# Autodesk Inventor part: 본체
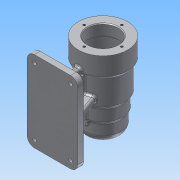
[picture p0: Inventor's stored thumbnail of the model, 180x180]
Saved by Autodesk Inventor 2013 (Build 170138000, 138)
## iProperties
Created: 2016-06
Part Number: 본체
Material: 알루미늄 6061
Document SubType Name: Modeling
Designer: Administrator
Density: 2.71 g/cm^3
Mass: 675.714 g
Surface Area: 653.039 cm^2
Volume: 249.341 cm^3
Author: Administrator
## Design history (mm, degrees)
sketch "스케치1"
  geometry: C1 r 34 at (0, 0); 1 further point
  constraints: 1 centre point, 1 coincident
  dimensions: "d0" = 68 diameter of C1
extrude "돌출1" new body sketch "스케치1" distance "d1" = 28; taper "d2" = 0 deg
sketch "스케치2"
  geometry: C1 r 34 at (0, 0) reference; C2 r 30 at (0, 0)
  constraints: 1 centre point, 1 coincident
  dimensions: "d3" = 60 diameter of C2
extrude "돌출2" join sketch "스케치2" distance "d4" = 39; taper "d5" = 0 deg
sketch "스케치3"
  geometry: C1 r 30 at (0, 0) reference; C2 r 27 at (0, 0)
  constraints: 1 centre point, 1 coincident
  dimensions: "d6" = 54 diameter of C2
extrude "돌출3" join sketch "스케치3" distance "d7" = 20; taper "d8" = 0 deg
sketch "스케치4"
  geometry: C1 r 27 at (0, 0) reference; C2 r 25 at (0, 0)
  constraints: 1 centre point, 1 coincident
  dimensions: "d9" = 50 diameter of C2
extrude "돌출4" join sketch "스케치4" distance "d10" = 25; taper "d11" = 0 deg
node "작업 평면1"
sketch "스케치5"
  geometry: L1 (-25, -84)-(25, -84) reference; L2 (35, -84)-(-35, -84); L3 (-35, -84)-(-35, 28); L4 (-35, 28)-(35, 28); L5 (35, 28)-(35, -84); 2 further points
  constraints: 8 end point, 2 parallel, 1 horizontal, 1 midpoint, 1 perpendicular, 1 vertical alignment
  dimensions: "d13" = 112 distance of L2.end L3.end; "d15" = 70 distance of L3.end L4.end; "d16" = 84 distance from line of point (0, 0) L2
extrude "돌출5" join sketch "스케치5" distance "d17" = 10; taper "d18" = 0 deg
hole "구멍1" diameter "d21" = 42; stored, may be unused: countersink angle "d25" = 90 deg, drill point angle "d27" = 0 deg; dims "d19" = 10, "d20" = 10, "d22" = 6, "d23" = 4, "d24" = 2, "d26" = 15
hole "구멍2" diameter "d30" = 42; stored, may be unused: countersink angle "d34" = 90 deg, drill point angle "d36" = 0 deg; dims "d28" = 10, "d29" = 10, "d31" = 6, "d32" = 48, "d33" = 54, "d35" = 66
hole "구멍3" diameter "d39" = 32; stored, may be unused: countersink angle "d43" = 90 deg, drill point angle "d45" = 0 deg; dims "d37" = 10, "d38" = 10, "d40" = 6, "d41" = 35, "d42" = 18, "d44" = 22
hole "구멍4" diameter "d48" = 21; stored, may be unused: countersink angle "d52" = 90 deg, drill point angle "d54" = 0 deg; dims "d46" = 10, "d47" = 10, "d49" = 6, "d50" = 2, "d51" = 18, "d53" = 3
sketch "스케치6"
  geometry: C1 r 21 at (0, 0) reference; 1 further point
  constraints: 1 vertical alignment
  dimensions: "d55" = 26 distance of C1.centre point (0, 26)
hole "구멍5" sketch "스케치6" at (0, 26) diameter "d56" = 3.242; stored, may be unused: countersink angle "d60" = 90 deg, drill point angle "d62" = 118 deg; dims "d57" = 8, "d58" = 2, "d59" = 18, "d61" = 11
fillet "모깎기1" dims "d66" = 10
sketch "스케치7"
  geometry: A1 r 10 centre (-25, 74) between (-25, 84) and (-35, 74) reference; A2 r 10 centre (-25, -18) between (-35, -18) and (-25, -28) reference; A3 r 10 centre (25, -18) between (25, -28) and (35, -18) reference; A4 r 10 centre (25, 74) between (35, 74) and (25, 84) reference; 5 further points
  constraints: 4 coincident
hole "구멍6" sketch "스케치7" at (-25, 74), (25, 74), (25, -18), (-25, -18) diameter "d67" = 5; stored, may be unused: countersink angle "d71" = 90 deg, drill point angle "d73" = 118 deg; dims "d68" = 8, "d69" = 9, "d70" = 4, "d72" = 11
sketch "스케치8"
  geometry: L1 (-25, -64)-(-60, -64); L2 (-70, 28)-(-60, 28) reference; L3 (-60, -84)-(-70, -84) reference; L4 (-34, 0)-(-34, 28) reference; L5 (-25, -59)-(-25, -84) reference; L6 (-60, -74)-(-60, 18) reference; 1 further point
  constraints: 2 end point, 2 point on line
  dimensions: "d75" = 20 distance between parallel lines of L3 L1
feature "리브1" sketch "스케치8" dims "d76" = 72, "d77" = 8, "d78" = 0, "d79" = 0, "d80" = 1, "d81" = 1
node "작업 평면2"
sketch "스케치9"
  geometry: L1 (-15.509, -25.68)-(-28, -60); L2 (-29.5, -60)-(-20.5, -60) reference; L3 (25, -60)-(-25, -60) reference; A1 r 30 centre (0, 0) between (4, -29.732) and (-4, -29.732) reference; 2 further points
  constraints: 2 end point, 1 point on circle, 1 point on line
  dimensions: "d83" = 110 deg angle of L2 L1; "d84" = 7 distance of L1.end point (-35, -60)
feature "리브2" sketch "스케치9" dims "d85" = 36, "d86" = 8, "d87" = 0, "d88" = 0, "d89" = 1, "d90" = 1
sketch "스케치10"
  geometry: L1 (15.509, -25.68)-(28, -60); L2 (25, -60)-(-25, -60) reference; L3 (20.5, -60)-(29.5, -60) reference; L4 (35, -60)-(35, -70) reference; L5 (25, -60)-(35, -60) reference; A1 r 30 centre (0, 0) between (4, -29.732) and (-4, -29.732) reference; 1 further point
  constraints: 2 end point, 1 point on circle, 1 point on line
  dimensions: "d92" = 7 distance from line of L4 L1.end; "d93" = 110 deg angle of L5 L1
feature "리브3" sketch "스케치10" dims "d94" = 36, "d95" = 8, "d96" = 0, "d97" = 0, "d98" = 1, "d99" = 1
chamfer "모따기1" distance "d100" = 2; stored, may be unused: second distance "d101" = 2, angle "d102" = 45 deg
fillet "모깎기2" dims "d103" = 10, "d104" = 0.3
node "작업 평면3"
sketch "스케치11"
  geometry: L1 (34, 28)-(-34, 28) reference; 3 further points
  constraints: 1 midpoint, 1 vertical alignment, 1 other
  dimensions: "d105" = 48 distance from line of point (0, -20) L1
feature "엠보싱1" sketch "스케치11" dims "d106" = 0.5, "d107" = 0
fillet "모깎기5" dims "d110" = 3
fillet "모깎기6" dims "d111" = 3
chamfer "모따기2" distance "d112" = 1; stored, may be unused: second distance "d113" = 2, angle "d114" = 45 deg
fillet "모깎기7" dims "d115" = 3
fillet "모깎기8" dims "d116" = 3
fillet "모깎기10" dims "d118" = 3, "d119" = 1
node "솔리드1"
pattern_circular "원형 패턴1" dims angle "d64" = 360 deg
other parameters: "d82" = -56
